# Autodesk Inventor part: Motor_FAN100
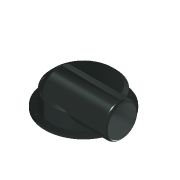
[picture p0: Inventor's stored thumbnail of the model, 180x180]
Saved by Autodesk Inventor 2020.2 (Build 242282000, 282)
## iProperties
Created: 2011-01
Part Number: Motor_FAN100
Document SubType Name: Modeling
Designer: F.Stasiak
Density: 1 g/cm^3
Material: Ogólny
Appearance: Brąz armatni — polerowany
Company: Fabian Stasiak CAD Consulting
Manager: www.cadconsulting.pl
Author: F.Stasiak
Subject: Zbiór ćwiczeń. Autodesk Inventor 2020. Kurs podstawowy
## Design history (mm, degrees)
sketch "Szkic1"
  geometry: C1 r 3.324 at (59.659, 123.883) reference; C2 r 3.324 at (107.502, 85.73) reference; C3 r 3.324 at (134.053, 30.597) reference; C4 r 3.324 at (134.053, -30.597) reference; C5 r 3.324 at (107.502, -85.73) reference; C6 r 3.324 at (59.659, -123.883) reference; C7 r 3.324 at (0, -137.5) reference; C8 r 3.324 at (-59.659, -123.883) reference; C9 r 3.324 at (-107.502, -85.73) reference; C10 r 3.324 at (-134.053, -30.597) reference; C11 r 3.324 at (-134.053, 30.597) reference; C12 r 3.324 at (-107.502, 85.73) reference; C13 r 3.324 at (-59.659, 123.883) reference; C14 r 3.324 at (0, 137.5) reference; C15 r 125 at (0, 0) reference; C16 r 150 at (0, 0) reference; C17 r 125 at (0, 0) reference; 1 further point
extrude "Wyciągnięcie proste1" new body sketch "Szkic1" distance "d0" = 10; taper "d1" = 0 deg
sketch "Szkic2"
  geometry: C1 r 125 at (0, 0) reference; 1 further point
extrude "Wyciągnięcie proste2" join sketch "Szkic2" distance "d2" = 80; taper "d3" = 0 deg
sketch "Szkic3"
  geometry: L1 (-125, 80)-(125, 80) reference; C1 r 65 at (-50.848, 80); 1 further point
  constraints: 1 centre point, 1 point on line
  dimensions: "d4" = 130 diameter of C1
extrude "Wyciągnięcie proste3" join sketch "Szkic3" distance "d5" = 200; taper "d6" = 0 deg
sketch "Szkic4"
  geometry: L1 (80, -115.848)-(80, 14.152) reference; A1 r 65 centre (80, -50.848) between (80, -115.848) and (80, 14.152) reference; 1 further point
extrude "Wyciągnięcie proste4" join sketch "Szkic4" distance "d7" = 50; taper "d8" = 0 deg
fillet "Zaokrąglenie1" dims "d9" = 10
fillet "Zaokrąglenie2" dims "d10" = 10
chamfer "Faza1" distance "d11" = 13; stored, may be unused: second distance "d12" = 2, angle "d13" = 45 deg
node "Bryła1"
node "Odniesienie1"
node "Odniesienie2"
node "Pętla rzutowana1"
